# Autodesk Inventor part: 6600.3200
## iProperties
Created: 2016-04
Part Number: 6600.3200
Checked By: TraceParts S.A.
Catalog Web Link: www.traceparts.com
Description: IEC appliance outlet F, screw-on mounting, front side, Quick-connect 4.8mm x 0.8mm
Vendor: SCHURTER
Document SubType Name: Modeling
Designer: TraceParts
Company: TraceParts S.A.
Title: IEC appliance outlet F, screw-on mounting, front side, Quick-connect 4.8mm x 0.8mm
Author: TraceParts
REFERENCE: 6600.3200
DESIGN: IEC appliance outlet F, screw-on mounting, front side, Quick-connect 4.8mm x 0.8mm
SUPPLIER: SCHURTER
TraceParts.PartNumber: 10-01092008-079714
TraceParts.PartTitle: Connectors 6600-3
TraceParts.InstanceId: 10-01092008-079714CETN7RUKH2PGGBKA05CF0H3L1
TraceParts.PartStatus: Published
TraceParts.PartVersion: 1.0.7
TRACEPARTS: TRACEPARTS
TraceParts.PartLanguage: en
TraceParts.ClassPath: SCHURTER:/F_SCHURTER/SCHURTER.020/SCHURTER.020.020/10-01092008-079714
